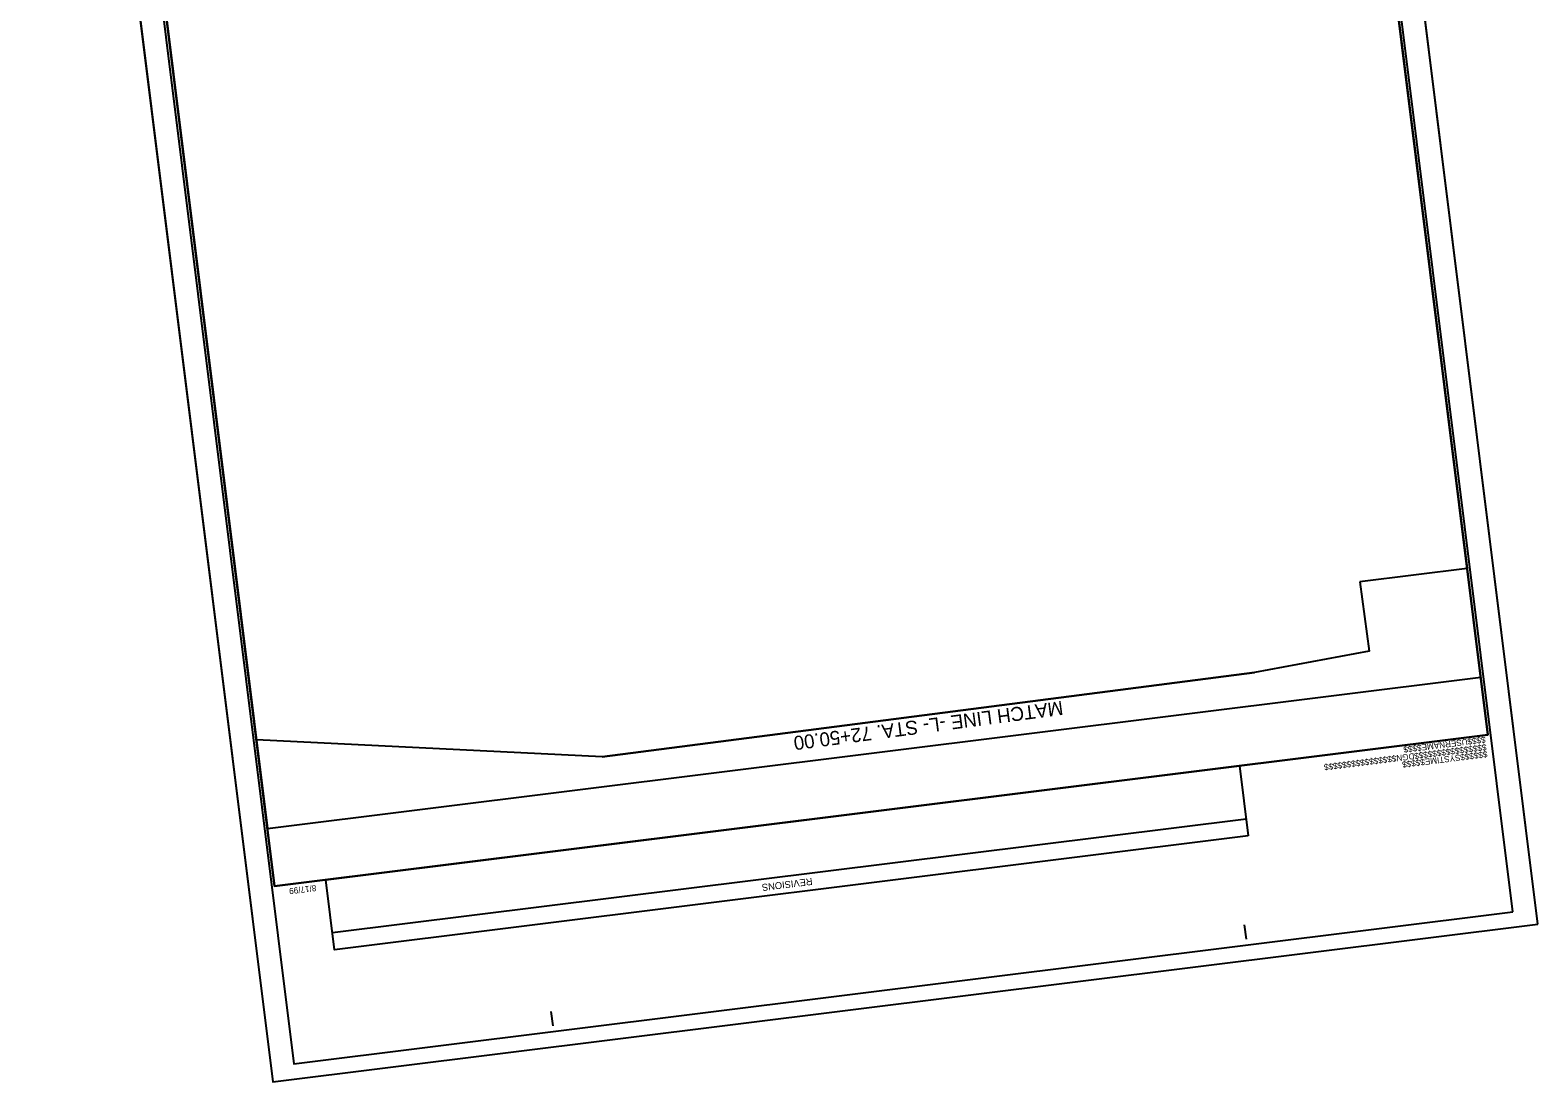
# Model space of a CAD drawing. Extents: x 2367685 to 2368979, y 807242 to 809048.
# Drawn here: x 2367685 to 2368979, y 807242 to 808145 of the extents above; entities that cross this region are included whole.
import ezdxf

# ---------------------------------------------------------------- set-up
doc = ezdxf.new("R2010")
doc.units = 0
for name, color, linetype in [('Old_Level_10', 7, 'Continuous'), ('Old_Level_15', 7, 'Continuous'), ('Old_Level_2', 7, 'Continuous'), ('Old_Level_22', 7, 'Continuous'), ('Old_Level_4', 7, 'Continuous'), ('Old_Level_6', 7, 'Continuous'), ('Old_Level_61', 7, 'Continuous'), ('Old_Level_62', 7, 'Continuous'), ('Plot Shape CELL', 7, 'Continuous'), ('User Information Notes CELL', 7, 'Continuous')]:
    doc.layers.add(name, color=color, linetype=linetype)

msp = doc.modelspace()

# ---------------------------------------------------------------- linework, layer by layer
at = {"layer": 'Old_Level_10'}
msp.add_lwpolyline([(2367894.5, 807409.7), (2368936.4, 807539.7), (2368750.9, 809028.1), (2367918.8, 808924.4), (2367948.4, 808687), (2367738.5, 808660.8)], close=True, dxfattribs=at)
at = {"layer": 'Old_Level_15'}
for p, q in [((2368979.4, 807377.2), (2368771.1, 809047.8)), ((2367684.5, 808912.3), (2367892.8, 807241.8)), ((2367892.8, 807241.8), (2368979.4, 807377.2))]:
    msp.add_line(p, q, dxfattribs=at)
at = {"layer": 'Old_Level_2'}
msp.add_lwpolyline([(2368930.3, 807589.3), (2368757.1, 808978.5), (2367925, 808874.8), (2367948.4, 808687), (2367738.5, 808660.8), (2367888.3, 807459.4)], close=True, dxfattribs=at)
at = {"layer": 'Old_Level_22'}
msp.add_lwpolyline([(2368826.6, 807671.1), (2368834.5, 807611.6), (2368735.9, 807593.2), (2368175.7, 807520.9), (2367878.9, 807535.5), (2367738.5, 808660.8), (2367948.4, 808687), (2367925, 808874.8), (2368757.1, 808978.5), (2368918.6, 807682.6)], close=True, dxfattribs=at)
msp.add_lwpolyline([(2368826.6, 807671.1), (2368834.5, 807611.6), (2368735.9, 807593.2), (2368175.7, 807520.9), (2367878.9, 807535.5), (2367738.5, 808660.8), (2367948.4, 808687), (2367925, 808874.8), (2368757.1, 808978.5), (2368918.6, 807682.6)], close=True, dxfattribs=at)
at = {"layer": 'Old_Level_4'}
msp.add_lwpolyline([(2368957.9, 807387.7), (2368751.8, 809040.8), (2367704.9, 808910.3), (2367911, 807257.1)], close=True, dxfattribs=at)
at = {"layer": 'Old_Level_6'}
msp.add_lwpolyline([(2368979.4, 807377.2), (2368771.1, 809047.8), (2367684.5, 808912.3), (2367892.8, 807241.8)], close=True, dxfattribs=at)
at = {"layer": 'Old_Level_62'}
msp.add_line((2368175.7, 807520.9), (2368735.9, 807593.2), dxfattribs=at)
at = {"layer": 'Plot Shape CELL'}
for p, q in [((2368936.4, 807539.7), (2368936.4, 807539.7)), ((2367894.5, 807409.8), (2367894.5, 807409.8)), ((2368729.1, 807364.2), (2368727.5, 807376.6)), ((2368133.7, 807289.9), (2368132.1, 807302.3))]:
    msp.add_line(p, q, dxfattribs=at)
for points in [[(2367708.9, 808898.3), (2367894.5, 807409.8), (2368936.4, 807539.7), (2368750.9, 809028.1)], [(2368936.4, 807539.7), (2367894.5, 807409.7), (2367733.7, 808699.7), (2367882.6, 808718.3), (2367857.8, 808916.8), (2368750.9, 809028.1)]]:
    msp.add_lwpolyline(points, close=True, dxfattribs=at)
at = {"layer": 'User Information Notes CELL'}
msp.add_line((2368728.8, 807467.4), (2367944.2, 807369.6), dxfattribs=at)
msp.add_lwpolyline([(2368730.6, 807453), (2367946, 807355.2), (2367938.5, 807415.3), (2368723.1, 807513.1)], close=True, dxfattribs=at)

# ---------------------------------------------------------------- texts
at = {"layer": 'Old_Level_61'}
msp.add_text('MATCH LINE -L- STA. 72+50.00', height=12, rotation=187.5263, dxfattribs=at).set_placement((2368570.8, 807568.9))
at = {"layer": 'Plot Shape CELL'}
for s, p in [('$$$$USERNAME$$$$', (2368934.2, 807538.3)), ('$$$$$$$$$$$$$$$$DGN$$$$$$$$$$$$$$$$', (2368935, 807531.8)), ('$$$$$$SYSTIME$$$$$', (2368935.8, 807525.8)), ('8/17/99', (2367929.9, 807410.9))]:
    msp.add_text(s, height=5.25, rotation=187.1063, dxfattribs=at).set_placement(p)
at = {"layer": 'User Information Notes CELL'}
msp.add_text('REVISIONS', height=6, rotation=187.1063, dxfattribs=at).set_placement((2368356, 807416.9))

doc.saveas('drawing.dxf')
